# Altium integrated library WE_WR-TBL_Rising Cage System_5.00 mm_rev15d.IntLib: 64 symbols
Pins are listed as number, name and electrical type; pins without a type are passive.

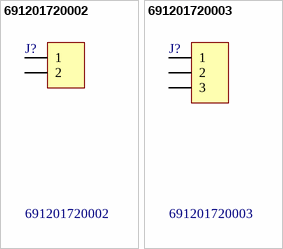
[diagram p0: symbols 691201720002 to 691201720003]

## 691201720002
designator J?
WR-TBL 45° Entry Modular with Rising Cage Clamp,Serie 201 - 5.00 mm; Manufacturer: Würth Elektronik eiSos GmbH; ComponentLink1 Description: Manufacturer; ComponentLink2 Description: Datasheet; NoPins: 2
footprint 691201720002 (5,00mm - modular - blue -45° entry with rising cage clamp - 02p)
pins: 1, 2

## 691201720003
designator J?
WR-TBL 45° Entry Modular with Rising Cage Clamp,Serie 201 - 5.00 mm; Manufacturer: Würth Elektronik eiSos GmbH; ComponentLink1 Description: Manufacturer; ComponentLink2 Description: Datasheet; NoPins: 3
footprint 691201720003 (5,00mm - modular - blue -45° entry with rising cage clamp - 03p)
pins: 1, 2, 3


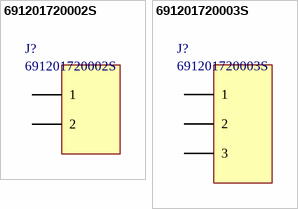
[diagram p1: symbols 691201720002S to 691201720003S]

## 691201720002S
designator J?
45° Cable Entry with Rising Cage Clamp, Serie 201S - 5.00 mm; Manufacturer: Wurth Elektronik; ComponentLink1 Description: Manufacturer; ComponentLink2 Description: Datasheet; NoPins: 2
footprint 691201720002S (Serie 201S - 5.00 mm _ 2 pins)
pins: 1, 2

## 691201720003S
designator J?
45° Cable Entry with Rising Cage Clamp, Serie 201S - 5.00 mm; Manufacturer: Wurth Elektronik; ComponentLink1 Description: Manufacturer; ComponentLink2 Description: Datasheet; NoPins: 3
footprint 691201720003S (Serie 201S - 5.00 mm _ 3 pins)
pins: 1, 2, 3


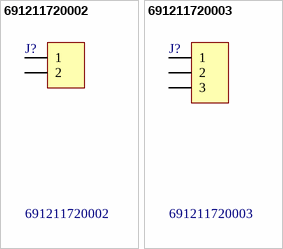
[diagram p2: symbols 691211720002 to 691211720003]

## 691211720002
designator J?
WR-TBL 45° Entry Modular with Rising Cage Clamp,Serie 211 - 5.00 mm - 15.5 mm Height; Manufacturer: Würth Elektronik eiSos GmbH; ComponentLink1 Description: Manufacturer; ComponentLink2 Description: Datasheet; NoPins: 2
footprint 691211720002 (5,00mm - modular - green -45° entry with rising cage clamp - 02p)
pins: 1, 2

## 691211720003
designator J?
WR-TBL 45° Entry Modular with Rising Cage Clamp,Serie 211 - 5.00 mm - 15.5 mm Height; Manufacturer: Würth Elektronik eiSos GmbH; ComponentLink1 Description: Manufacturer; ComponentLink2 Description: Datasheet; NoPins: 3
footprint 691211720003 (5,00mm - modular - green -45° entry with rising cage clamp - 03p)
pins: 1, 2, 3


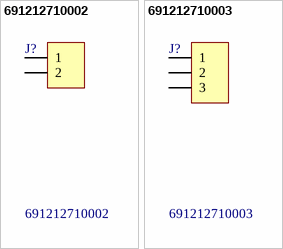
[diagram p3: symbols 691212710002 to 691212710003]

## 691212710002
designator J?
WR-TBL Horizontal Entry Modular with Rising Cage Clamp,Serie 212 - 5.00 mm; Manufacturer: Würth Elektronik eiSos GmbH; ComponentLink1 Description: Manufacturer; ComponentLink2 Description: Datasheet; NoPins: 2
footprint 691212710002 (5,00mm - modular - green - Horizontal entry with rising cage clamp -  14,3mm height - 02p)
pins: 1, 2

## 691212710003
designator J?
WR-TBL Horizontal Entry Modular with Rising Cage Clamp,Serie 212 - 5.00 mm; Manufacturer: Würth Elektronik eiSos GmbH; ComponentLink1 Description: Manufacturer; ComponentLink2 Description: Datasheet; NoPins: 3
footprint 691212710003 (5,00mm - modular - green - Horizontal entry with rising cage clamp -  14,3mm height - 03p)
pins: 1, 2, 3


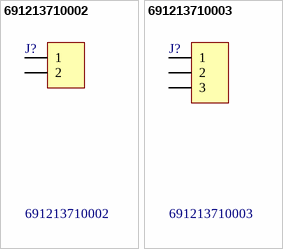
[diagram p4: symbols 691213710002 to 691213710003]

## 691213710002
designator J?
WR-TBL Horizontal Entry Modular with Rising Cage Clamp,Serie 213 - 5.00 mm; Manufacturer: Würth Elektronik eiSos GmbH; ComponentLink1 Description: Manufacturer; ComponentLink2 Description: Datasheet; NoPins: 2
footprint 691213710002 (5,00mm - modular - green - Horizontal entry with rising cage clamp -  10,0mm height - 02p)
pins: 1, 2

## 691213710003
designator J?
WR-TBL Horizontal Entry Modular with Rising Cage Clamp,Serie 213 - 5.00 mm; Manufacturer: Würth Elektronik eiSos GmbH; ComponentLink1 Description: Manufacturer; ComponentLink2 Description: Datasheet; NoPins: 3
footprint 691213710003 (5,00mm - modular - green - Horizontal entry with rising cage clamp -  10,0mm height - 03p)
pins: 1, 2, 3


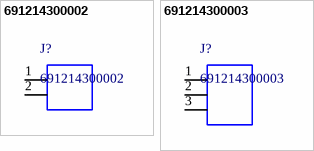
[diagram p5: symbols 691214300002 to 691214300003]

## 691214300002
designator J?
WR-TBL Vertical Cable Entry With Rising Cage Clamp,Serie 2143 - 3.81 mm; Manufacturer: Wurth Elektronik; ComponentLink1 Description: Manufacturer; ComponentLink2 Description: Datasheet
footprint 691214300002 (Serie 2143 - 3.81 mm _ 2 pins)
pins: 1, 2

## 691214300003
designator J?
WR-TBL Vertical Cable Entry With Rising Cage Clamp,Serie 2143 - 3.81 mm; Manufacturer: Wurth Elektronik; ComponentLink1 Description: Manufacturer; ComponentLink2 Description: Datasheet
footprint 691214300003 (Serie 2143 - 3.81 mm _ 3 pins)
pins: 1, 2, 3


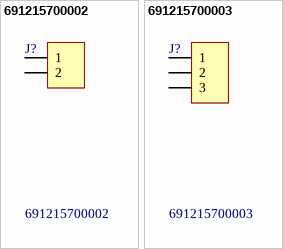
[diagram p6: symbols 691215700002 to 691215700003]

## 691215700002
designator J?
WR-TBL Vertical Entry Modular with Rising Cage Clamp,Serie 2157 - 5.00 mm; Manufacturer: Würth Elektronik eiSos GmbH; ComponentLink1 Description: Manufacturer; ComponentLink2 Description: Datasheet; NoPins: 2
footprint 691215700002
pins: 1, 2

## 691215700003
designator J?
WR-TBL Vertical Entry Modular with Rising Cage Clamp,Serie 2157 - 5.00 mm; Manufacturer: Würth Elektronik eiSos GmbH; ComponentLink1 Description: Manufacturer; ComponentLink2 Description: Datasheet; NoPins: 3
footprint 691215700003
pins: 1, 2, 3


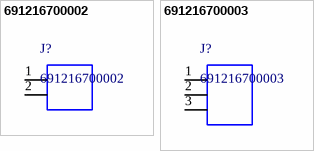
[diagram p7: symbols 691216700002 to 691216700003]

## 691216700002
designator J?
WR-TBL Vertical Cable Entry With Rising Cage Clamp,Serie 2167 - 5.00 mm; Manufacturer: Wurth Elektronik; ComponentLink1 Description: Manufacturer; ComponentLink2 Description: Datasheet
footprint 691216700002 (Serie 2167 - 5.00 mm _ 2 pins)
pins: 1, 2

## 691216700003
designator J?
WR-TBL Vertical Cable Entry With Rising Cage Clamp,Serie 2167 - 5.00 mm; Manufacturer: Wurth Elektronik; ComponentLink1 Description: Manufacturer; ComponentLink2 Description: Datasheet
footprint 691216700003 (Serie 2167 - 5.00 mm _ 3 pins)
pins: 1, 2, 3


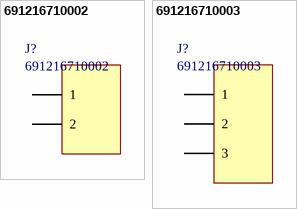
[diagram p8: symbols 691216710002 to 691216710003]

## 691216710002
designator J?
Horizontal Cable Entry with Rising Cage Clamp, Serie 2167 - 5.00 mm; Manufacturer: Wurth Elektronik; ComponentLink1 Description: Manufacturer; ComponentLink2 Description: Datasheet; NoPins: 2
footprint 691216710002 (Serie 2167 - 5.00 mm _ 2 pins)
pins: 1, 2

## 691216710003
designator J?
Horizontal Cable Entry with Rising Cage Clamp, Serie 2167 - 5.00 mm; Manufacturer: Wurth Elektronik; ComponentLink1 Description: Manufacturer; ComponentLink2 Description: Datasheet; NoPins: 3
footprint 691216710003 (Serie 2167 - 5.00 mm _ 3 pins)
pins: 1, 2, 3


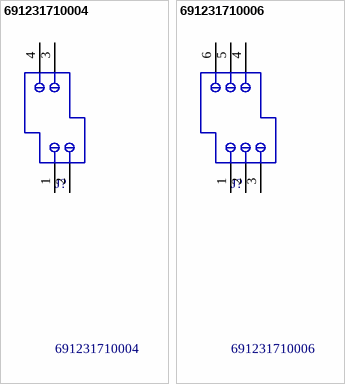
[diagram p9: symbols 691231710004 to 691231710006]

## 691231710004
designator J?
WR-TBL Double Level Horizontal Entry Modular with Rising Clamp,Serie 2317 - 5.00 mm; Manufacturer: Würth Elektronik eiSos GmbH; ComponentLink1 Description: Manufacturer; ComponentLink2 Description: Datasheet; NoPins: 4
footprint 691231710004 (5,00mm - modular - 2 rows - Right - horizontal entry with rising cage clamp - 04p - h=19,1mm)
pins: 1, 2, 3, 4

## 691231710006
designator J?
WR-TBL Double Level Horizontal Entry Modular with Rising Clamp,Serie 2317 - 5.00 mm; Manufacturer: Würth Elektronik eiSos GmbH; ComponentLink1 Description: Manufacturer; ComponentLink2 Description: Datasheet; NoPins: 6
footprint 691231710006 (5,00mm - modular - 2 rows - Right - horizontal entry with rising cage clamp - 06p - h=19,1mm)
pins: 1, 2, 3, 4, 5, 6


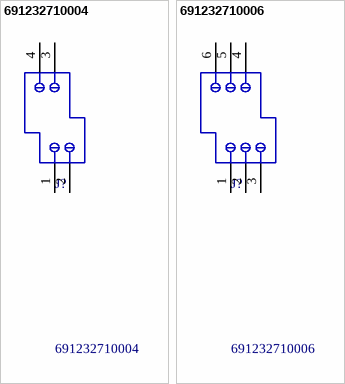
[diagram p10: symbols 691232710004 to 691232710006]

## 691232710004
designator J?
WR-TBL Double Level Horizontal Entry Modular with Rising Clamp,Serie 2327 - 5.00 mm; Manufacturer: Würth Elektronik eiSos GmbH; ComponentLink1 Description: Manufacturer; ComponentLink2 Description: Datasheet; NoPins: 4
footprint 691232710004 (5,00mm - modular - 2 rows - Right - horizontal entry with rising cage clamp - 04p - h=25,3mm)
pins: 1, 2, 3, 4

## 691232710006
designator J?
WR-TBL Double Level Horizontal Entry Modular with Rising Clamp,Serie 2327 - 5.00 mm; Manufacturer: Würth Elektronik eiSos GmbH; ComponentLink1 Description: Manufacturer; ComponentLink2 Description: Datasheet; NoPins: 6
footprint 691232710006 (5,00mm - modular - 2 rows - Right - horizontal entry with rising cage clamp - 06p - h=25,3mm)
pins: 1, 2, 3, 4, 5, 6


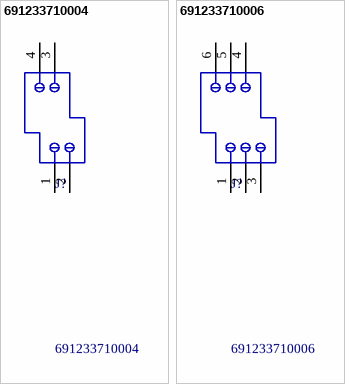
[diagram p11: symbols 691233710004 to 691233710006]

## 691233710004
designator J?
WR-TBL Double Level Horizontal Entry Modular with Rising Clamp,Serie 2337 - 5.00 mm; Manufacturer: Würth Elektronik eiSos GmbH; ComponentLink1 Description: Manufacturer; ComponentLink2 Description: Datasheet; NoPins: 4
footprint 691233710004 (5,00mm - modular - 2 rows - Right - horizontal entry with rising cage clamp - 04p - h=31,5mm)
pins: 1, 2, 3, 4

## 691233710006
designator J?
WR-TBL Double Level Horizontal Entry Modular with Rising Clamp,Serie 2337 - 5.00 mm; Manufacturer: Würth Elektronik eiSos GmbH; ComponentLink1 Description: Manufacturer; ComponentLink2 Description: Datasheet; NoPins: 6
footprint 691233710006 (5,00mm - modular - 2 rows - Right - horizontal entry with rising cage clamp - 06p - h=31,5mm)
pins: 1, 2, 3, 4, 5, 6


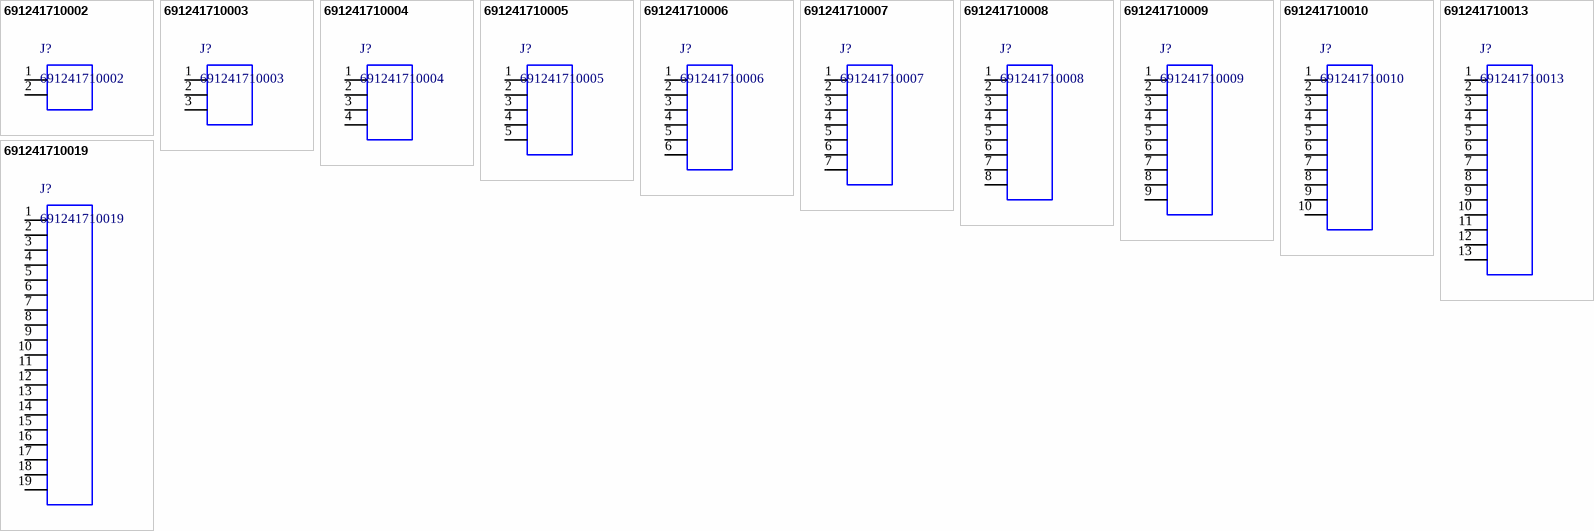
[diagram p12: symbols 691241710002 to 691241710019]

## 691241710002
designator J?
WR-TBL Horizontal Cable Entry With Rising Cage Clamp,Serie 2417 - 5.00 mm; Manufacturer: Wurth Elektronik; ComponentLink1 Description: Manufacturer; ComponentLink2 Description: Datasheet
footprint 691241710002 (Serie 2417 - 5.00 mm _ 2 pins)
pins: 1, 2

## 691241710003
designator J?
WR-TBL Horizontal Cable Entry With Rising Cage Clamp,Serie 2417 - 5.00 mm; Manufacturer: Wurth Elektronik; ComponentLink1 Description: Manufacturer; ComponentLink2 Description: Datasheet
footprint 691241710003 (Serie 2417 - 5.00 mm _ 3 pins)
pins: 1, 2, 3

## 691241710004
designator J?
WR-TBL Horizontal Cable Entry With Rising Cage Clamp,Serie 2417 - 5.00 mm; Manufacturer: Wurth Elektronik; ComponentLink1 Description: Manufacturer; ComponentLink2 Description: Datasheet
footprint 691241710004 (Serie 2417 - 5.00 mm _ 4 pins)
pins: 1, 2, 3, 4

## 691241710005
designator J?
WR-TBL Horizontal Cable Entry With Rising Cage Clamp,Serie 2417 - 5.00 mm; Manufacturer: Wurth Elektronik; ComponentLink1 Description: Manufacturer; ComponentLink2 Description: Datasheet
footprint 691241710005 (Serie 2417 - 5.00 mm _ 5 pins)
pins: 1, 2, 3, 4, 5

## 691241710006
designator J?
WR-TBL Horizontal Cable Entry With Rising Cage Clamp,Serie 2417 - 5.00 mm; Manufacturer: Wurth Elektronik; ComponentLink1 Description: Manufacturer; ComponentLink2 Description: Datasheet
footprint 691241710006 (Serie 2417 - 5.00 mm _ 6 pins)
pins: 1, 2, 3, 4, 5, 6

## 691241710007
designator J?
WR-TBL Horizontal Cable Entry With Rising Cage Clamp,Serie 2417 - 5.00 mm; Manufacturer: Wurth Elektronik; ComponentLink1 Description: Manufacturer; ComponentLink2 Description: Datasheet
footprint 691241710007 (Serie 2417 - 5.00 mm _ 7 pins)
pins: 1, 2, 3, 4, 5, 6, 7

## 691241710008
designator J?
WR-TBL Horizontal Cable Entry With Rising Cage Clamp,Serie 2417 - 5.00 mm; Manufacturer: Wurth Elektronik; ComponentLink1 Description: Manufacturer; ComponentLink2 Description: Datasheet
footprint 691241710008 (Serie 2417 - 5.00 mm _ 8 pins)
pins: 1, 2, 3, 4, 5, 6, 7, 8

## 691241710009
designator J?
WR-TBL Horizontal Cable Entry With Rising Cage Clamp,Serie 2417 - 5.00 mm; Manufacturer: Wurth Elektronik; ComponentLink1 Description: Manufacturer; ComponentLink2 Description: Datasheet
footprint 691241710009 (Serie 2417 - 5.00 mm _ 9 pins)
pins: 1, 2, 3, 4, 5, 6, 7, 8, 9

## 691241710010
designator J?
WR-TBL Horizontal Cable Entry With Rising Cage Clamp,Serie 2417 - 5.00 mm; Manufacturer: Wurth Elektronik; ComponentLink1 Description: Manufacturer; ComponentLink2 Description: Datasheet
footprint 691241710010 (Serie 2417 - 5.00 mm _ 10 pins)
pins: 1, 2, 3, 4, 5, 6, 7, 8, 9, 10

## 691241710013
designator J?
WR-TBL Horizontal Cable Entry With Rising Cage Clamp,Serie 2417 - 5.00 mm; Manufacturer: Wurth Elektronik; ComponentLink1 Description: Manufacturer; ComponentLink2 Description: Datasheet
footprint 691241710013 (Serie 2417 - 5.00 mm _ 13 pins)
pins: 1, 2, 3, 4, 5, 6, 7, 8, 9, 10, 11, 12, 13

## 691241710019
designator J?
WR-TBL Horizontal Cable Entry With Rising Cage Clamp,Serie 2417 - 5.00 mm; Manufacturer: Wurth Elektronik; ComponentLink1 Description: Manufacturer; ComponentLink2 Description: Datasheet
footprint 691241710019 (Serie 2417 - 5.00 mm _ 19 pins)
pins: 1, 2, 3, 4, 5, 6, 7, 8, 9, 10, 11, 12, 13, 14, 15, 16, 17, 18, 19


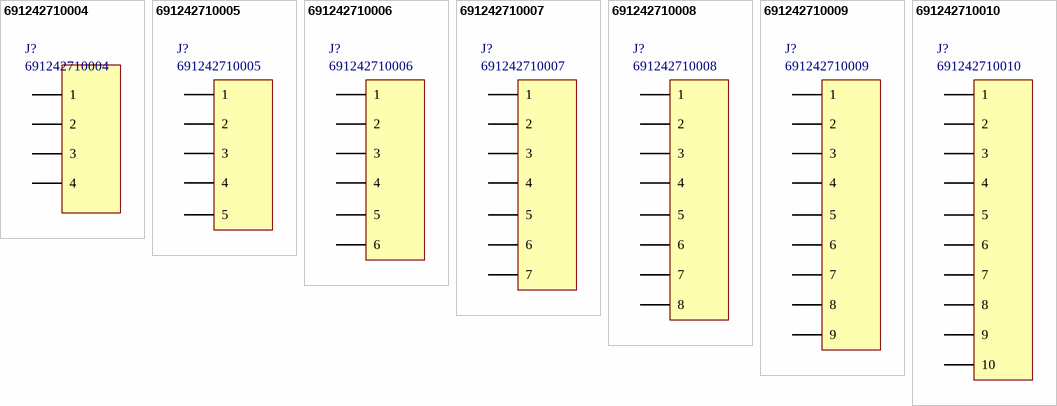
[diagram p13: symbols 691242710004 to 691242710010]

## 691242710004
designator J?
Horizontal Cable Entry with Rising Cage Clamp, Serie 2427 - 5.00 mm; Manufacturer: Wurth Elektronik; ComponentLink1 Description: Manufacturer; ComponentLink2 Description: Datasheet; NoPins: 4
footprint 691242710004 (Serie 2427 - 5.00 mm_4 pins)
pins: 1, 2, 3, 4

## 691242710005
designator J?
Horizontal Cable Entry with Rising Cage Clamp, Serie 2427 - 5.00 mm; Manufacturer: Wurth Elektronik; ComponentLink1 Description: Manufacturer; ComponentLink2 Description: Datasheet; NoPins: 5
footprint 691242710005 (Serie 2427 - 5.00 mm_5 pins)
pins: 1, 2, 3, 4, 5

## 691242710006
designator J?
Horizontal Cable Entry with Rising Cage Clamp, Serie 2427 - 5.00 mm; Manufacturer: Wurth Elektronik; ComponentLink1 Description: Manufacturer; ComponentLink2 Description: Datasheet; NoPins: 6
footprint 691242710006 (Serie 2427 - 5.00 mm_6 pins)
pins: 1, 2, 3, 4, 5, 6

## 691242710007
designator J?
Horizontal Cable Entry with Rising Cage Clamp, Serie 2427 - 5.00 mm; Manufacturer: Wurth Elektronik; ComponentLink1 Description: Manufacturer; ComponentLink2 Description: Datasheet; NoPins: 7
footprint 691242710007 (Serie 2427 - 5.00 mm_7 pins)
pins: 1, 2, 3, 4, 5, 6, 7

## 691242710008
designator J?
Horizontal Cable Entry with Rising Cage Clamp, Serie 2427 - 5.00 mm; Manufacturer: Wurth Elektronik; ComponentLink1 Description: Manufacturer; ComponentLink2 Description: Datasheet; NoPins: 8
footprint 691242710008 (Serie 2427 - 5.00 mm_8 pins)
pins: 1, 2, 3, 4, 5, 6, 7, 8

## 691242710009
designator J?
Horizontal Cable Entry with Rising Cage Clamp, Serie 2427 - 5.00 mm; Manufacturer: Wurth Elektronik; ComponentLink1 Description: Manufacturer; ComponentLink2 Description: Datasheet; NoPins: 9
footprint 691242710009 (Serie 2427 - 5.00 mm_9 pins)
pins: 1, 2, 3, 4, 5, 6, 7, 8, 9

## 691242710010
designator J?
Horizontal Cable Entry with Rising Cage Clamp, Serie 2427 - 5.00 mm; Manufacturer: Wurth Elektronik; ComponentLink1 Description: Manufacturer; ComponentLink2 Description: Datasheet; NoPins: 10
footprint 691242710010 (Serie 2427 - 5.00 mm_10 pins)
pins: 1, 2, 3, 4, 5, 6, 7, 8, 9, 10


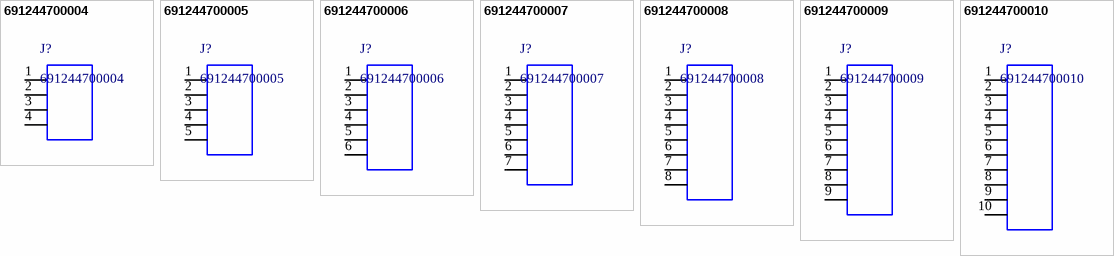
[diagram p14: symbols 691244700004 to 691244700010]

## 691244700004
designator J?
WR-TBL Vertical Cable Entry With Rising Cage Clamp,Serie 2447 - 5.00 mm; Manufacturer: Wurth Elektronik; ComponentLink1 Description: Manufacturer; ComponentLink2 Description: Datasheet
footprint 691244700004 (Serie 2447 - 5.00 mm _ 4 pins)
pins: 1, 2, 3, 4

## 691244700005
designator J?
WR-TBL Vertical Cable Entry With Rising Cage Clamp,Serie 2447 - 5.00 mm; Manufacturer: Wurth Elektronik; ComponentLink1 Description: Manufacturer; ComponentLink2 Description: Datasheet
footprint 691244700005 (Serie 2447 - 5.00 mm _ 5 pins)
pins: 1, 2, 3, 4, 5

## 691244700006
designator J?
WR-TBL Vertical Cable Entry With Rising Cage Clamp,Serie 2447 - 5.00 mm; Manufacturer: Wurth Elektronik; ComponentLink1 Description: Manufacturer; ComponentLink2 Description: Datasheet
footprint 691244700006 (Serie 2447 - 5.00 mm _ 6 pins)
pins: 1, 2, 3, 4, 5, 6

## 691244700007
designator J?
WR-TBL Vertical Cable Entry With Rising Cage Clamp,Serie 2447 - 5.00 mm; Manufacturer: Wurth Elektronik; ComponentLink1 Description: Manufacturer; ComponentLink2 Description: Datasheet
footprint 691244700007 (Serie 2447 - 5.00 mm _ 7 pins)
pins: 1, 2, 3, 4, 5, 6, 7

## 691244700008
designator J?
WR-TBL Vertical Cable Entry With Rising Cage Clamp,Serie 2447 - 5.00 mm; Manufacturer: Wurth Elektronik; ComponentLink1 Description: Manufacturer; ComponentLink2 Description: Datasheet
footprint 691244700008 (Serie 2447 - 5.00 mm _ 8 pins)
pins: 1, 2, 3, 4, 5, 6, 7, 8

## 691244700009
designator J?
WR-TBL Vertical Cable Entry With Rising Cage Clamp,Serie 2447 - 5.00 mm; Manufacturer: Wurth Elektronik; ComponentLink1 Description: Manufacturer; ComponentLink2 Description: Datasheet
footprint 691244700009 (Serie 2447 - 5.00 mm _ 9 pins)
pins: 1, 2, 3, 4, 5, 6, 7, 8, 9

## 691244700010
designator J?
WR-TBL Vertical Cable Entry With Rising Cage Clamp,Serie 2447 - 5.00 mm; Manufacturer: Wurth Elektronik; ComponentLink1 Description: Manufacturer; ComponentLink2 Description: Datasheet
footprint 691244700010 (Serie 2447 - 5.00 mm _ 10 pins)
pins: 1, 2, 3, 4, 5, 6, 7, 8, 9, 10


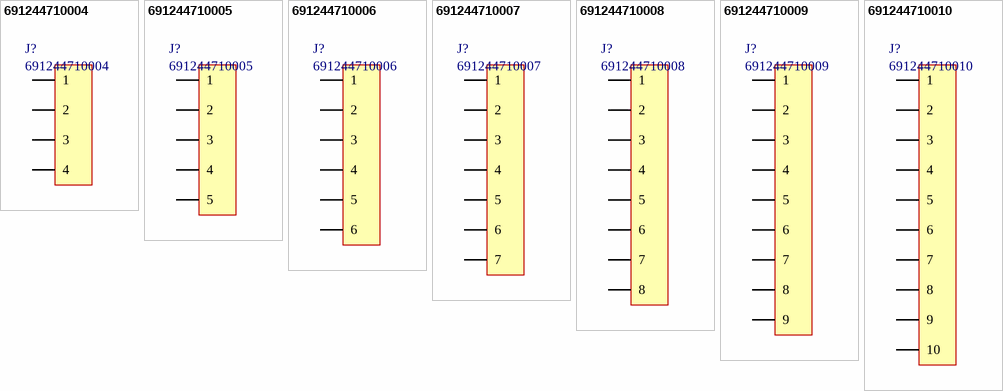
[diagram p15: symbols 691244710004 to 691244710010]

## 691244710004
designator J?
Horizontal Cable Entry with Rising Cage Clamp, Serie 2447 - 5mm; Manufacturer: Wurth Elektronik; ComponentLink1 Description: Manufacturer; ComponentLink2 Description: Datasheet; NoPins: 4
footprint 691244710004 (Serie 2447 - 5.00 mm _ 4 pins)
pins: 1, 2, 3, 4

## 691244710005
designator J?
Horizontal Cable Entry with Rising Cage Clamp, Serie 2447 - 5mm; Manufacturer: Wurth Elektronik; ComponentLink1 Description: Manufacturer; ComponentLink2 Description: Datasheet; NoPins: 5
footprint 691244710005 (Serie 2447 - 5.00 mm _ 5 pins)
pins: 1, 2, 3, 4, 5

## 691244710006
designator J?
Horizontal Cable Entry with Rising Cage Clamp, Serie 2447 - 5mm; Manufacturer: Wurth Elektronik; ComponentLink1 Description: Manufacturer; ComponentLink2 Description: Datasheet; NoPins: 6
footprint 691244710006 (Serie 2447 - 5.00 mm _ 6 pins)
pins: 1, 2, 3, 4, 5, 6

## 691244710007
designator J?
Horizontal Cable Entry with Rising Cage Clamp, Serie 2447 - 5mm; Manufacturer: Wurth Elektronik; ComponentLink1 Description: Manufacturer; ComponentLink2 Description: Datasheet; NoPins: 7
footprint 691244710007 (Serie 2447 - 5.00 mm _ 7 pins)
pins: 1, 2, 3, 4, 5, 6, 7

## 691244710008
designator J?
Horizontal Cable Entry with Rising Cage Clamp, Serie 2447 - 5mm; Manufacturer: Wurth Elektronik; ComponentLink1 Description: Manufacturer; ComponentLink2 Description: Datasheet; NoPins: 8
footprint 691244710008 (Serie 2447 - 5.00 mm _ 8 pins)
pins: 1, 2, 3, 4, 5, 6, 7, 8

## 691244710009
designator J?
Horizontal Cable Entry with Rising Cage Clamp, Serie 2447 - 5mm; Manufacturer: Wurth Elektronik; ComponentLink1 Description: Manufacturer; ComponentLink2 Description: Datasheet; NoPins: 9
footprint 691244710009 (Serie 2447 - 5.00 mm _ 9 pins)
pins: 1, 2, 3, 4, 5, 6, 7, 8, 9

## 691244710010
designator J?
Horizontal Cable Entry with Rising Cage Clamp, Serie 2447 - 5mm; Manufacturer: Wurth Elektronik; ComponentLink1 Description: Manufacturer; ComponentLink2 Description: Datasheet; NoPins: 10
footprint 691244710010 (Serie 2447 - 5.00 mm _ 10 pins)
pins: 1, 2, 3, 4, 5, 6, 7, 8, 9, 10


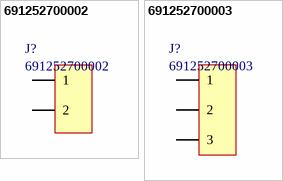
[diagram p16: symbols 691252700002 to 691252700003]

## 691252700002
designator J?
Horizontal Cable Entry with Rising Cage Clamp, Serie 2527 - 5mm; Manufacturer: Wurth Elektronik; ComponentLink1 Description: Manufacturer; ComponentLink2 Description: Datasheet; NoPins: 2
footprint 691252700002 (Serie 2527 - 5.00 mm _ 2 pins)
pins: 1, 2

## 691252700003
designator J?
Horizontal Cable Entry with Rising Cage Clamp, Serie 2527 - 5mm; Manufacturer: Wurth Elektronik; ComponentLink1 Description: Manufacturer; ComponentLink2 Description: Datasheet; NoPins: 3
footprint 691252700003 (Serie 2527 - 5.00 mm _ 3 pins)
pins: 1, 2, 3


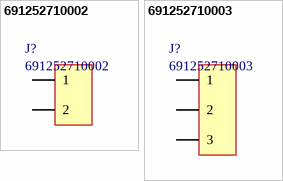
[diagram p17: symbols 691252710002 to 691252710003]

## 691252710002
designator J?
Horizontal Cable Entry with Rising Cage Clamp, Serie 2527 - 5mm; Manufacturer: Wurth Elektronik; ComponentLink1 Description: Manufacturer; ComponentLink2 Description: Datasheet; NoPins: 2
footprint 691252710002 (Serie 2527 - 5.00 mm _ 2 pins)
pins: 1, 2

## 691252710003
designator J?
Horizontal Cable Entry with Rising Cage Clamp, Serie 2527 - 5mm; Manufacturer: Wurth Elektronik; ComponentLink1 Description: Manufacturer; ComponentLink2 Description: Datasheet; NoPins: 3
footprint 691252710003 (Serie 2527 - 5.00 mm _ 3 pins)
pins: 1, 2, 3


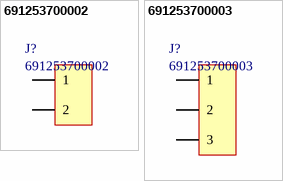
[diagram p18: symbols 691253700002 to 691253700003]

## 691253700002
designator J?
Horizontal Cable Entry with Rising Cage Clamp, Serie 2537 - 5mm; Manufacturer: Wurth Elektronik; ComponentLink1 Description: Manufacturer; ComponentLink2 Description: Datasheet; NoPins: 2
footprint 691253700002 (Serie 2537 - 5.00 mm _ 2 pins)
pins: 1, 2

## 691253700003
designator J?
Horizontal Cable Entry with Rising Cage Clamp, Serie 2537 - 5mm; Manufacturer: Wurth Elektronik; ComponentLink1 Description: Manufacturer; ComponentLink2 Description: Datasheet; NoPins: 3
footprint 691253700003 (Serie 2537 - 5.00 mm _ 3 pins)
pins: 1, 2, 3


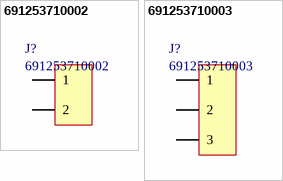
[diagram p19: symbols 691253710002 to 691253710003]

## 691253710002
designator J?
Horizontal Cable Entry with Rising Cage Clamp, Serie 2537 - 5mm; Manufacturer: Wurth Elektronik; ComponentLink1 Description: Manufacturer; ComponentLink2 Description: Datasheet; NoPins: 2
footprint 691253710002 (Serie 2537 - 5.00 mm _ 2 pins)
pins: 1, 2

## 691253710003
designator J?
Horizontal Cable Entry with Rising Cage Clamp, Serie 2537 - 5mm; Manufacturer: Wurth Elektronik; ComponentLink1 Description: Manufacturer; ComponentLink2 Description: Datasheet; NoPins: 3
footprint 691253710003 (Serie 2537 - 5.00 mm _ 3 pins)
pins: 1, 2, 3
